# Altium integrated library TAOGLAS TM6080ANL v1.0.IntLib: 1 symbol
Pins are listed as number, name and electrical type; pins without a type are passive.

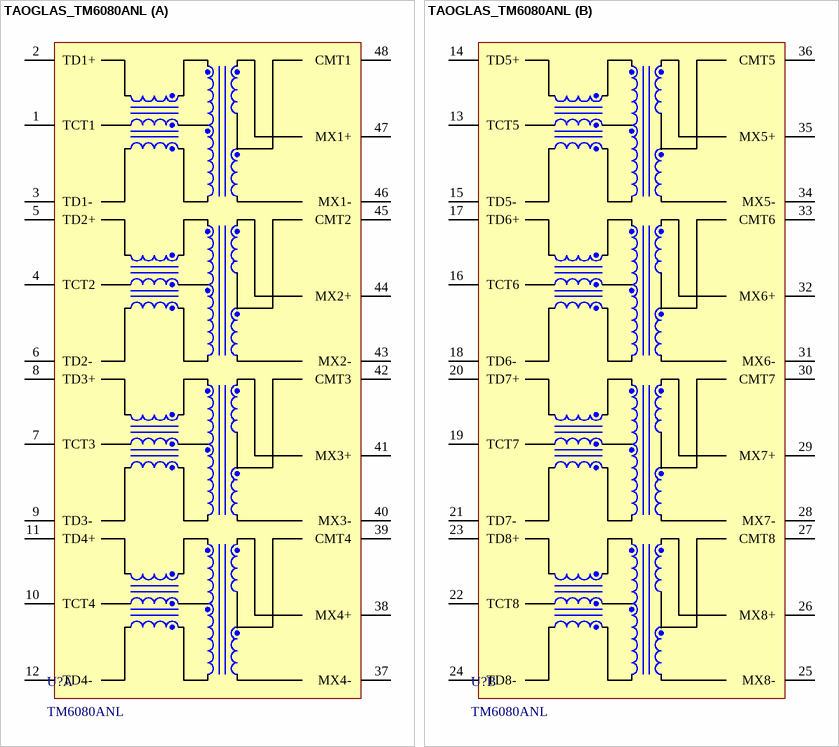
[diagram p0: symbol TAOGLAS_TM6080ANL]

## TAOGLAS_TM6080ANL
designator U?, comment TM6080ANL
1G Base-T transformer Dual Port and 48 pin SMT; ComponentLibStatus: Created; MFG: Taoglas; Temp_High: +85C; Temp_Low: -40C
footprint TAOGLAS_TM6080ANL (1G Base-T transformer Dual Port and 48 pin SMT)
part A pins: 1 TCT1, 2 TD1+, 3 TD1-, 4 TCT2, 5 TD2+, 6 TD2-, 7 TCT3, 8 TD3+, 9 TD3-, 10 TCT4, 11 TD4+, 12 TD4-, 37 MX4-, 38 MX4+, 39 CMT4, 40 MX3-, 41 MX3+, 42 CMT3, 43 MX2-, 44 MX2+, 45 CMT2, 46 MX1-, 47 MX1+, 48 CMT1
part B pins: 13 TCT5, 14 TD5+, 15 TD5-, 16 TCT6, 17 TD6+, 18 TD6-, 19 TCT7, 20 TD7+, 21 TD7-, 22 TCT8, 23 TD8+, 24 TD8-, 25 MX8-, 26 MX8+, 27 CMT8, 28 MX7-, 29 MX7+, 30 CMT7, 31 MX6-, 32 MX6+, 33 CMT6, 34 MX5-, 35 MX5+, 36 CMT5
